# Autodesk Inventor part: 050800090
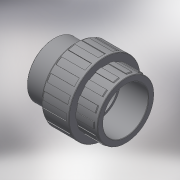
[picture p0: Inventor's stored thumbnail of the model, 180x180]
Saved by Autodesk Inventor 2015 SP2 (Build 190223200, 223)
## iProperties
Created: 2017-10
Part Number: 050800090
Material: Generic
Description: PLASSON UNION+O RING-CEM PVC 90
Document SubType Name: Modeling
Designer: Кирилл
Density: 1 g/cm^3
Appearance: Default
Author: Кирилл
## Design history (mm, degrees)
derived "050800.ipt"
feature "Solid1::050800.ipt"
tag "TaggingFeature1"
body "Solid1"
other parameters: "d0" = 125, "d5" = 108, "d6" = 112.5, "d7" = 115.2, "d8" = 132, "d9" = 51, "d10" = 51, "d11" = 81, "d12" = 85.5, "d14" = 38.25, "d15" = 38.25, "d16" = 20.7, "d17" = 5.1, "d19" = 129.36, "d20" = 5.1, "d21" = 3.96, "d25" = 13.2, "d26" = 6.6, "d27" = 39.06, "d28" = 0, "d32" = 13.2, "d33" = 6.6, "d35" = 0, "d39" = 0.9, "d45" = 1.35, "d49" = 360 deg, "d51" = 1.32, "d55" = 360 deg, "E_" = 132, "H_" = 125, "l_" = 51, "l_1" = 51, "Z_" = 23, "d13" = 23, "d24" = 43.4, "d40" = 1.35, "d44" = 1.32
